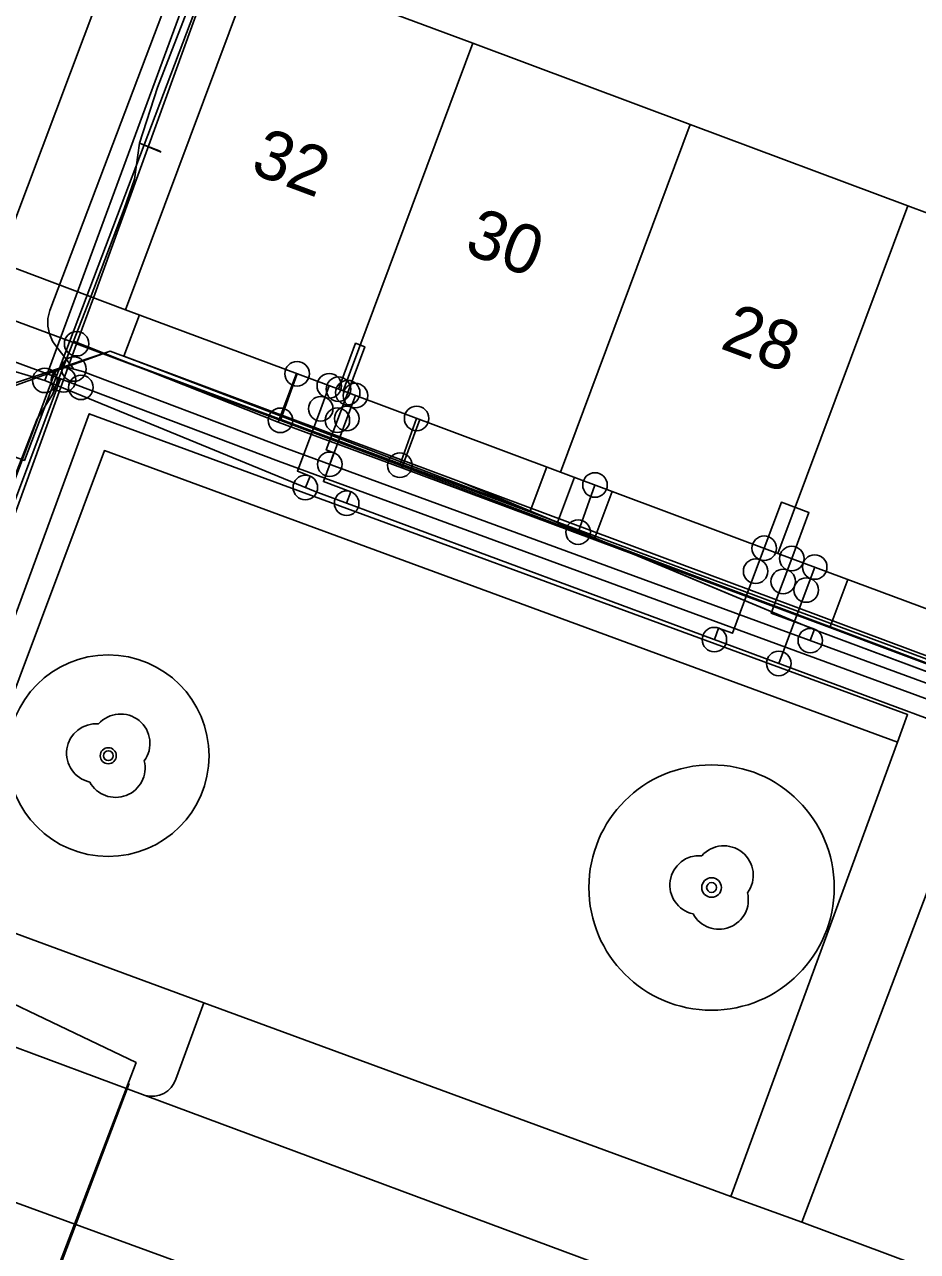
# Model space of a CAD drawing. Extents: x 192672 to 192910, y 446344 to 446512.
# Drawn here: x 192750.68 to 192768.88, y 446392.71 to 446417.71 of the extents above; entities that cross this region are included whole.
import ezdxf

# ---------------------------------------------------------------- set-up
doc = ezdxf.new("R2010")
doc.units = 0
for name, color, linetype in [('( Toegevoegd 29-11-2021 14_41_42) ondersteunend wegdeel vlak', 7, 'Continuous'), ('( Toegevoegd 29-11-2021 14_41_42) wegdeel vlak', 7, 'Continuous'), ('B-GV-GR-BOOM-S', 7, 'Continuous'), ('B-OI-KL-BUISLEIDING_OLIEGASCHEMICALIEN_GASLAGEDRUK-G', 7, 'Continuous'), ('B-OI-KL-DATA-G', 7, 'Continuous'), ('B-OI-KL-DATA_GTWP-S', 7, 'Continuous'), ('B-OI-KL-DATA_KABELBED-G', 7, 'Continuous'), ('B-OI-KL-DATA_MOF-S', 7, 'Continuous'), ('B-OI-KL-ET_LS-G', 7, 'Continuous'), ('B-OI-KL-ET_LS_AARDING-S', 7, 'Continuous'), ('B-OI-KL-ET_LS_DELIVERYPOINT-S', 7, 'Continuous'), ('B-OI-KL-ET_LS_MANTELBUIS-G', 7, 'Continuous'), ('B-OI-KL-ET_LS_MOF-S', 7, 'Continuous'), ('B-OI-KL-ET_MS-G', 7, 'Continuous'), ('B-OI-KL-GAS_LD_AFTAKZADEL-S', 7, 'Continuous'), ('B-OI-KL-GAS_LD_DELIVERYPOINT-S', 7, 'Continuous'), ('B-OI-KL-GAS_LD_OVERGANGSSTUK-S', 7, 'Continuous'), ('B-OI-KL-GAS_LD_TSTUK-S', 7, 'Continuous'), ('B-OI-KL-WATER-G', 7, 'Continuous'), ('B-OI-RI-RIOOLVRIJVERVAL-G', 7, 'Continuous'), ('boom', 7, 'Continuous'), ('Default', 7, 'Continuous'), ('huisnummerreeks BGT', 7, 'Continuous'), ('kant open verharding', 7, 'Continuous'), ('kant verharding', 7, 'Continuous'), ('pand op maaiveld vlak', 7, 'Continuous'), ('verkeerseiland - berm', 7, 'Continuous')]:
    doc.layers.add(name, color=color, linetype=linetype)

# ---------------------------------------------------------------- blocks, each defined once
blk = doc.blocks.new('B-OI-KL-ET_LS_AARDING-S')
at = {"layer": 'Default'}
blk.add_circle((0, 0), 0.25, dxfattribs=at)
blk = doc.blocks.new('B-OI-KL-GAS_LD_AFTAKZADEL-S')
at = {"layer": 'Default'}
blk.add_circle((0, 0), 0.25, dxfattribs=at)
blk = doc.blocks.new('B-OI-KL-GAS_LD_DELIVERYPOINT-S')
at = {"layer": 'Default'}
blk.add_circle((0, 0), 0.25, dxfattribs=at)
blk = doc.blocks.new('B-OI-KL-GAS_LD_OVERGANGSSTUK-S')
at = {"layer": 'Default'}
blk.add_circle((0, 0), 0.25, dxfattribs=at)
blk = doc.blocks.new('B-OI-KL-GAS_LD_TSTUK-S')
at = {"layer": 'Default'}
blk.add_circle((0, 0), 0.25, dxfattribs=at)
blk = doc.blocks.new('B-OI-KL-ET_LS_DELIVERYPOINT-S')
at = {"layer": 'Default'}
blk.add_circle((0, 0), 0.25, dxfattribs=at)
blk = doc.blocks.new('B-OI-KL-ET_LS_MOF-S')
at = {"layer": 'Default'}
blk.add_circle((0, 0), 0.25, dxfattribs=at)
blk = doc.blocks.new('B-OI-KL-DATA_GTWP-S')
at = {"layer": 'Default'}
blk.add_circle((0, 0), 0.25, dxfattribs=at)
blk = doc.blocks.new('B-OI-KL-DATA_MOF-S')
at = {"layer": 'Default'}
blk.add_circle((0, 0), 0.25, dxfattribs=at)

msp = doc.modelspace()

# ---------------------------------------------------------------- linework, layer by layer
at = {"layer": '( Toegevoegd 29-11-2021 14_41_42) ondersteunend wegdeel vlak'}
for p, q in [((192754.334, 446397.778), (192753.763, 446396.222)), ((192750.175, 446396.992), (192753.133, 446395.89))]:
    msp.add_line(p, q, dxfattribs=at)
msp.add_arc((192753.27, 446396.393), 0.522, 254.7293, 340.8478, dxfattribs=at)
at = {"layer": '( Toegevoegd 29-11-2021 14_41_42) wegdeel vlak'}
msp.add_lwpolyline([(192768.471, 446403.091), (192768.677, 446403.651), (192751.996, 446409.781), (192748.388, 446399.963)], dxfattribs=at)
at = {"layer": 'B-GV-GR-BOOM-S'}
for centre, radius in [((192752.383, 446402.813), 2.054), ((192752.383, 446402.813), 0.164), ((192764.68, 446400.127), 2.5), ((192764.68, 446400.127), 0.2)]:
    msp.add_circle(centre, radius, dxfattribs=at)
at = {"layer": 'B-OI-KL-BUISLEIDING_OLIEGASCHEMICALIEN_GASLAGEDRUK-G'}
for points in [[(192808.99, 446509.756), (192805.748, 446508.276), (192801.187, 446506.24), (192794.261, 446502.995), (192789.059, 446500.595), (192784.967, 446498.672), (192784.158, 446498.207), (192778.689, 446484.216), (192775.51, 446475.031), (192756.472, 446424.494), (192754.598, 446419.974), (192751.089, 446410.462)], [(192751.089, 446410.462), (192750.084, 446410.758), (192742.909, 446413.369), (192742.217, 446413.618)], [(192825.926, 446382.49), (192824.393, 446382.916), (192820.049, 446384.609), (192801.561, 446391.312), (192784.629, 446397.804), (192756.601, 446408.196), (192751.089, 446410.462)], [(192756.713, 446409.883), (192756.888, 446410.352)], [(192757.245, 446409.684), (192757.421, 446410.153)], [(192756.4, 446408.279), (192756.495, 446408.51), (192756.24, 446408.615), (192756.713, 446409.883)], [(192757.242, 446407.958), (192757.329, 446408.193), (192756.767, 446408.401), (192757.245, 446409.684)], [(192765.578, 446406.573), (192765.753, 446407.042)], [(192764.738, 446405.179), (192764.825, 446405.414), (192765.106, 446405.309), (192765.578, 446406.573)], [(192766.609, 446406.189), (192766.783, 446406.658)], [(192766.05, 446404.693), (192766.609, 446406.189)]]:
    msp.add_lwpolyline(points, dxfattribs=at)
at = {"layer": 'B-OI-KL-DATA-G'}
for points in [[(192675.743, 446430.36), (192720.2, 446413.771), (192739.906, 446406.53), (192752.421, 446411.058), (192770.152, 446404.44), (192773.577, 446403.064), (192825.629, 446383.71), (192826.856, 446388.539), (192834.171, 446407.983), (192839.017, 446421.742), (192838.042, 446426.7), (192842.865, 446440.095), (192846.683, 446450.008), (192848.26, 446453.903), (192848.365, 446454.374), (192848.254, 446454.945), (192844.011, 446462.681), (192860.643, 446470.952)], [(192753.019, 446415.296), (192753.389, 446416.428), (192755.111, 446420.888), (192753.608, 446421.506), (192747.333, 446423.998), (192746.061, 446424.511), (192745.619, 446424.697), (192745.237, 446423.754), (192744.239, 446422.5), (192741.607, 446415.471), (192741.284, 446414.993), (192740.849, 446413.811), (192740.953, 446413.129), (192738.997, 446408.143), (192738.51, 446407.367), (192737.667, 446407.73)], [(192755.111, 446420.888), (192753.389, 446416.428), (192753.019, 446415.296), (192752.917, 446414.565), (192752.705, 446413.957), (192752.017, 446412.131), (192751.673, 446411.261), (192755.847, 446409.612)], [(192753.019, 446415.296), (192752.917, 446414.565), (192752.705, 446413.957), (192752.017, 446412.131), (192751.673, 446411.261)], [(192824.206, 446384.09), (192811.77, 446388.666), (192800.57, 446392.879), (192794.37, 446395.227), (192792.126, 446396.049), (192784.25, 446399.016), (192782.007, 446399.854), (192781.923, 446399.917), (192775.819, 446402.157), (192773.839, 446402.894), (192767.092, 446405.423), (192758.368, 446408.679), (192755.847, 446409.612), (192751.673, 446411.261), (192752.017, 446412.131), (192752.705, 446413.957), (192752.917, 446414.565), (192753.019, 446415.296), (192753.444, 446415.13)], [(192753.462, 446415.112), (192753.019, 446415.296)], [(192789.27, 446401.796), (192789.647, 446401.655), (192788.074, 446397.442), (192766.817, 446405.364), (192759.575, 446408.388), (192752.702, 446410.953), (192753.017, 446411.796)], [(192789.27, 446401.796), (192789.647, 446401.655), (192788.074, 446397.442), (192766.817, 446405.364), (192759.575, 446408.388), (192752.702, 446410.953), (192753.017, 446411.796)], [(192751.673, 446411.261), (192751.244, 446410.174), (192750.935, 446409.68), (192750.147, 446407.673), (192750.467, 446406.312), (192749.5, 446403.782), (192748.987, 446403.342), (192747.735, 446399.921), (192747.259, 446399.193), (192746.924, 446398.578), (192744.851, 446393.422), (192744.761, 446392.29), (192744.458, 446390.955), (192740.313, 446379.795), (192737.259, 446371.63), (192734.058, 446363.201), (192730.017, 446352.288), (192729.223, 446350.283), (192728.827, 446349.172), (192727.477, 446345.556)], [(192751.673, 446411.261), (192755.847, 446409.612), (192758.368, 446408.679), (192767.092, 446405.423), (192773.839, 446402.894), (192775.819, 446402.157), (192782.007, 446399.854), (192784.25, 446399.016), (192792.126, 446396.049), (192794.37, 446395.227), (192800.57, 446392.879), (192811.77, 446388.666), (192824.206, 446384.09), (192824.805, 446383.834)], [(192755.847, 446409.612), (192756.217, 446410.602)], [(192755.847, 446409.612), (192758.368, 446408.679), (192758.735, 446409.662)], [(192789.27, 446401.796), (192789.647, 446401.655), (192788.074, 446397.442), (192766.817, 446405.364), (192760.986, 446407.799), (192761.321, 446408.697)], [(192789.27, 446401.796), (192789.647, 446401.655), (192788.074, 446397.442), (192766.817, 446405.364), (192761.54, 446407.568), (192761.883, 446408.487)], [(192767.092, 446405.423), (192762.289, 446407.216), (192762.656, 446408.198)], [(192767.092, 446405.423), (192767.459, 446406.406)], [(192773.839, 446402.894), (192767.092, 446405.423)]]:
    msp.add_lwpolyline(points, dxfattribs=at)
at = {"layer": 'B-OI-KL-DATA_KABELBED-G'}
for points in [[(192781.5, 446489.931), (192778.594, 446482.476), (192777.525, 446479.682), (192775.942, 446475.544), (192774.287, 446471.219), (192774.071, 446470.654), (192771.264, 446463.317), (192769.537, 446458.803), (192769.421, 446458.498), (192766.199, 446450.043), (192761.064, 446436.566), (192759.105, 446431.427), (192758.318, 446429.36), (192752.08, 446412.145), (192751.738, 446411.209)], [(192751.471, 446410.473), (192743.029, 446413.584), (192741.714, 446414.036)], [(192752.702, 446410.953), (192753.017, 446411.796)], [(192751.738, 446411.209), (192751.471, 446410.472)], [(192821.01, 446385.323), (192810.079, 446389.386), (192802.298, 446392.278), (192800.939, 446392.783), (192793.524, 446395.538), (192789.077, 446397.191), (192779.512, 446400.781), (192775.099, 446402.438), (192774.537, 446402.649), (192761.96, 446407.369), (192758.326, 446408.733), (192752.386, 446410.963), (192751.738, 446411.209)], [(192752.702, 446410.953), (192760.986, 446407.799)], [(192751.471, 446410.472), (192747.546, 446399.65), (192744.75, 446391.942)], [(192755.892, 446409.648), (192756.232, 446410.597)], [(192758.326, 446408.733), (192758.668, 446409.687)], [(192760.986, 446407.799), (192761.321, 446408.697)], [(192761.54, 446407.568), (192761.883, 446408.487)], [(192761.96, 446407.369), (192762.304, 446408.33)], [(192760.986, 446407.799), (192761.54, 446407.568)], [(192761.54, 446407.568), (192766.817, 446405.364), (192769.767, 446404.265)]]:
    msp.add_lwpolyline(points, dxfattribs=at)
at = {"layer": 'B-OI-KL-ET_LS-G'}
for points in [[(192751.683, 446410.693), (192751.297, 446411.193), (192751.249, 446411.263), (192751.183, 446411.41), (192751.151, 446411.568), (192751.154, 446411.72), (192751.195, 446411.884), (192761.82, 446439.945), (192769.713, 446460.045), (192776.093, 446476.975), (192777.923, 446482.086)], [(192751.683, 446410.693), (192751.864, 446410.643), (192755.959, 446409.097), (192774.392, 446402.333), (192793.329, 446395.227), (192810.936, 446388.57), (192825.501, 446383.221), (192828.633, 446391.683), (192830.747, 446397.998), (192835.074, 446409.537), (192839.277, 446421.313), (192839.311, 446421.965), (192838.716, 446427.358), (192842.595, 446438.42)], [(192759.938, 446436.632), (192760.07, 446436.515), (192761.052, 446436.201), (192750.674, 446408.83), (192749.898, 446409.114), (192749.734, 446409.092)], [(192751.683, 446410.693), (192751.552, 446410.731), (192751.472, 446410.738), (192751.395, 446410.716), (192751.332, 446410.668), (192751.29, 446410.599), (192748.269, 446402.545), (192740.519, 446405.455), (192737.866, 446406.039), (192687.696, 446424.966), (192675.743, 446429.685)], [(192757.263, 446410.212), (192757.612, 446411.149), (192757.425, 446411.219), (192757.075, 446410.282)], [(192737.952, 446406.43), (192740.605, 446405.846), (192746.455, 446403.697), (192748.549, 446402.864), (192751.41, 446410.493), (192755.854, 446408.816), (192774.3, 446402.047), (192793.219, 446394.948), (192807.287, 446389.624)], [(192757.053, 446409.65), (192757.263, 446410.212)], [(192756.898, 446408.752), (192756.984, 446408.987), (192756.827, 446409.045), (192757.053, 446409.65)], [(192749.964, 446388.741), (192752.949, 446396.558), (192748.401, 446398.738), (192747.595, 446400.775), (192747.643, 446404.187), (192749.734, 446409.092)], [(192766.315, 446406.832), (192766.665, 446407.769), (192766.103, 446407.979), (192765.753, 446407.042)], [(192766.14, 446406.364), (192766.315, 446406.832)], [(192766.693, 446405.158), (192766.779, 446405.393), (192765.898, 446405.716), (192766.14, 446406.364)]]:
    msp.add_lwpolyline(points, dxfattribs=at)
at = {"layer": 'B-OI-KL-ET_LS_MANTELBUIS-G'}
msp.add_lwpolyline([(192752.807, 446396.132), (192750.817, 446390.873)], dxfattribs=at)
at = {"layer": 'B-OI-KL-ET_MS-G'}
msp.add_lwpolyline([(192675.743, 446430.392), (192719.08, 446414.198), (192720.2, 446413.771), (192739.907, 446406.53), (192740.419, 446406.767), (192749.859, 446410.199), (192752.421, 446411.058), (192770.152, 446404.44), (192774.571, 446402.692), (192787.766, 446397.768), (192806.764, 446390.772), (192825.096, 446383.91)], dxfattribs=at)
at = {"layer": 'B-OI-KL-WATER-G'}
msp.add_lwpolyline([(192742.681, 446414.565), (192743.85, 446414.136), (192825.105, 446383.994)], dxfattribs=at)
at = {"layer": 'B-OI-RI-RIOOLVRIJVERVAL-G'}
msp.add_lwpolyline([(192740.63, 446397.31), (192757.91, 446391)], dxfattribs=at)
at = {"layer": 'boom'}
for centre in [(192752.383, 446402.813), (192764.68, 446400.127)]:
    msp.add_circle(centre, 0.1, dxfattribs=at)
for centre, radius, start, end in [((192752.133, 446402.863), 0.6, 85.137, 257.7544), ((192752.633, 446403.063), 0.6, 323.5446, 138.4658), ((192752.533, 446402.563), 0.6, 208.5058, 13.8356), ((192752.383, 446402.813), 0.1, 0, 180), ((192752.383, 446402.813), 0.1, 180, 0), ((192764.93, 446400.377), 0.6, 323.5446, 138.4658), ((192764.43, 446400.177), 0.6, 85.137, 257.7544), ((192764.68, 446400.127), 0.1, 0, 180), ((192764.83, 446399.877), 0.6, 208.5058, 13.8356), ((192764.68, 446400.127), 0.1, 180, 0)]:
    msp.add_arc(centre, radius, start, end, dxfattribs=at)
at = {"layer": 'kant open verharding'}
msp.add_line((192750.151, 446412.873), (192752.736, 446411.901), dxfattribs=at)
at = {"layer": 'kant verharding'}
for p, q in [((192750.151, 446412.873), (192753.421, 446421.556)), ((192753.133, 446395.89), (192813.567, 446373.412)), ((192765.07, 446393.833), (192766.521, 446393.307))]:
    msp.add_line(p, q, dxfattribs=at)
at = {"layer": 'pand op maaiveld vlak'}
for p, q in [((192752.736, 446411.901), (192755.381, 446418.987)), ((192755.381, 446418.987), (192759.813, 446417.332)), ((192759.813, 446417.332), (192757.169, 446410.247)), ((192764.246, 446415.677), (192759.813, 446417.332)), ((192761.602, 446408.592), (192764.246, 446415.677)), ((192768.678, 446414.021), (192764.246, 446415.677)), ((192768.678, 446414.021), (192766.034, 446406.937)), ((192752.736, 446411.901), (192757.169, 446410.247)), ((192761.602, 446408.592), (192757.169, 446410.247)), ((192766.034, 446406.937), (192761.602, 446408.592)), ((192766.034, 446406.937), (192770.467, 446405.283))]:
    msp.add_line(p, q, dxfattribs=at)
msp.add_lwpolyline([(192773.128, 446412.468), (192773.093, 446412.373), (192768.678, 446414.021)], dxfattribs=at)
at = {"layer": 'verkeerseiland - berm'}
for p, q in [((192768.471, 446403.091), (192765.07, 446393.833)), ((192770.009, 446402.51), (192766.521, 446393.307)), ((192748.841, 446399.796), (192754.334, 446397.778)), ((192754.334, 446397.778), (192765.07, 446393.833)), ((192783.608, 446386.92), (192766.521, 446393.307))]:
    msp.add_line(p, q, dxfattribs=at)
msp.add_lwpolyline([(192748.841, 446399.796), (192752.303, 446409.032), (192768.471, 446403.091)], dxfattribs=at)

# ---------------------------------------------------------------- block references
at = {"layer": 'B-OI-KL-DATA_GTWP-S'}
for p in [(192751.738, 446411.209), (192751.738, 446411.209), (192751.738, 446411.209), (192751.471, 446410.473), (192751.471, 446410.472), (192751.471, 446410.472), (192756.232, 446410.597), (192758.668, 446409.687), (192755.892, 446409.648), (192758.326, 446408.733), (192762.304, 446408.33), (192761.96, 446407.369)]:
    msp.add_blockref('B-OI-KL-DATA_GTWP-S', p, dxfattribs=at)
at = {"layer": 'B-OI-KL-DATA_MOF-S'}
for p in [(192755.892, 446409.648), (192758.326, 446408.733), (192761.96, 446407.369)]:
    msp.add_blockref('B-OI-KL-DATA_MOF-S', p, dxfattribs=at)
at = {"layer": 'B-OI-KL-ET_LS_AARDING-S'}
msp.add_blockref('B-OI-KL-ET_LS_AARDING-S', (192751.825, 446410.32), dxfattribs=at)
at = {"layer": 'B-OI-KL-ET_LS_DELIVERYPOINT-S'}
for p in [(192757.075, 446410.282), (192757.263, 446410.212), (192765.753, 446407.042), (192766.315, 446406.832)]:
    msp.add_blockref('B-OI-KL-ET_LS_DELIVERYPOINT-S', p, dxfattribs=at)
at = {"layer": 'B-OI-KL-ET_LS_MOF-S'}
for p in [(192751.683, 446410.693), (192757.053, 446409.65), (192756.898, 446408.752), (192766.14, 446406.364), (192766.693, 446405.158)]:
    msp.add_blockref('B-OI-KL-ET_LS_MOF-S', p, dxfattribs=at)
at = {"layer": 'B-OI-KL-GAS_LD_AFTAKZADEL-S'}
for p in [(192756.4, 446408.279), (192757.242, 446407.958), (192764.738, 446405.179), (192766.05, 446404.693)]:
    msp.add_blockref('B-OI-KL-GAS_LD_AFTAKZADEL-S', p, dxfattribs=at)
at = {"layer": 'B-OI-KL-GAS_LD_DELIVERYPOINT-S'}
for p in [(192756.888, 446410.352), (192757.421, 446410.153), (192765.753, 446407.042), (192766.783, 446406.658)]:
    msp.add_blockref('B-OI-KL-GAS_LD_DELIVERYPOINT-S', p, dxfattribs=at)
at = {"layer": 'B-OI-KL-GAS_LD_OVERGANGSSTUK-S'}
for p in [(192756.713, 446409.883), (192757.245, 446409.684), (192765.578, 446406.573), (192766.609, 446406.189)]:
    msp.add_blockref('B-OI-KL-GAS_LD_OVERGANGSSTUK-S', p, dxfattribs=at)
at = {"layer": 'B-OI-KL-GAS_LD_TSTUK-S'}
msp.add_blockref('B-OI-KL-GAS_LD_TSTUK-S', (192751.089, 446410.462), dxfattribs=at)

# ---------------------------------------------------------------- texts
at = {"layer": 'huisnummerreeks BGT'}
for s, p in [('32', (192755.251, 446414.698)), ('30', (192759.611, 446413.071)), ('28', (192764.829, 446411.123))]:
    msp.add_text(s, height=1, rotation=339.6, dxfattribs=at).set_placement(p)

doc.saveas('drawing.dxf')
